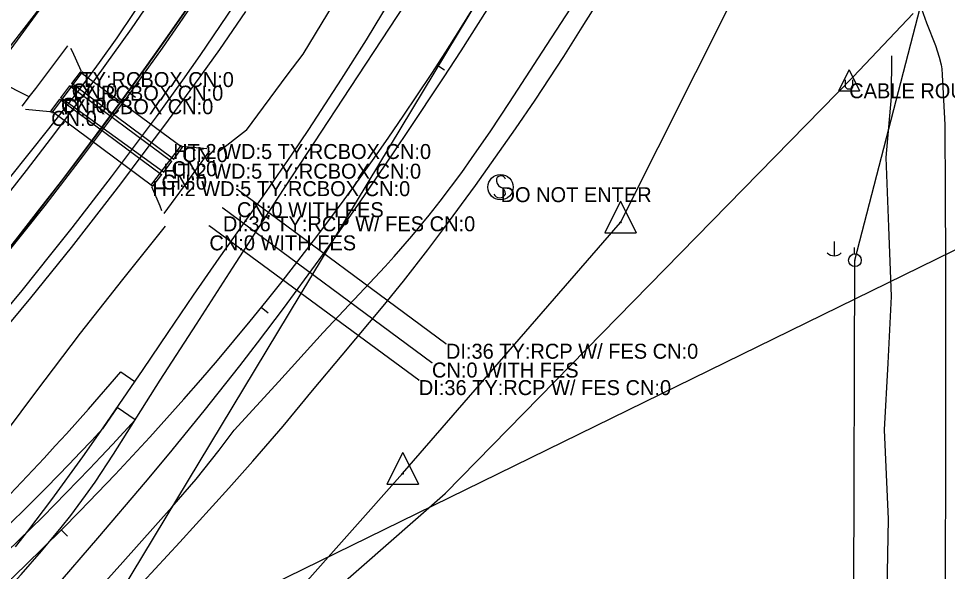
# Model space of a CAD drawing. Extents: x 1674300 to 1677920, y 225056 to 231852.
# Drawn here: x 1677063.6 to 1677374.1, y 227976.6 to 228161.2 of the extents above; entities that cross this region are included whole.
import ezdxf

# ---------------------------------------------------------------- set-up
doc = ezdxf.new("R2010")
doc.units = 0
for name, color, linetype in [('R_Horz Alg', 7, 'Continuous'), ('R_Horz Alg Annot', 7, 'Continuous'), ('R_Proposed Const Limits_Fill', 7, 'Continuous'), ('R_Proposed Road_Lane', 7, 'Continuous'), ('R_Proposed Road_Shoulder', 7, 'Continuous'), ('S_CROSS_DRAIN', 7, 'Continuous'), ('S_CROSS_DRAIN_ANNOT', 7, 'Continuous'), ('S_DITCHLINE', 7, 'Continuous'), ('S_DRG_PT_SYM', 7, 'Continuous'), ('S_EDGE_CONCRETE', 7, 'Continuous'), ('S_EDGE_PAVEMENT', 7, 'Continuous'), ('S_ELECTRIC_UTILITIES', 7, 'Continuous'), ('S_EXIST_ROW', 7, 'Continuous'), ('S_EXISTING_ALIGNMENT', 7, 'Continuous'), ('S_FIBER_OPTIC_CABLE', 7, 'Continuous'), ('S_HEADWALL', 7, 'Continuous'), ('S_PAVEMENT_CROWN', 7, 'Continuous'), ('S_SHOULDER', 7, 'Continuous'), ('S_SIGN', 7, 'Continuous'), ('S_SIGN_ANNOT', 7, 'Continuous'), ('S_UNDERGROUND_CABLE', 7, 'Continuous'), ('S_UTILITY_POLE', 7, 'Continuous'), ('S_UTILITY_POLE_ANNOT', 7, 'Continuous'), ('S_UTL_PT_SYM', 7, 'Continuous'), ('S_WALL', 7, 'Continuous')]:
    doc.layers.add(name, color=color, linetype=linetype)

msp = doc.modelspace()

# ---------------------------------------------------------------- linework, layer by layer
at = {"layer": 'R_Horz Alg'}
for centre, radius, end in [((1675928.16, 228988.54), 1449, 0.80558), ((1676402.48, 228665.51), 954.93, 328.88259)]:
    msp.add_arc(centre, radius, 296.0624, end, dxfattribs=at)
at = {"layer": 'R_Horz Alg Annot'}
for p, q in [((1677074.66, 227931.25), (1677220, 228172.01)), ((1676564.78, 227686.88), (1677389.93, 228090.45))]:
    msp.add_line(p, q, dxfattribs=at)
for points in [[(1677205.98, 228143.96), (1677203.46, 228145.59)], [(1677102.65, 228134.8), (1677100.23, 228136.57)], [(1677147.06, 228062.83), (1677144.73, 228064.72)], [(1677079.98, 227988.3), (1677077.86, 227990.42)]]:
    msp.add_lwpolyline(points, dxfattribs=at)
at = {"layer": 'R_Proposed Const Limits_Fill'}
msp.add_line((1677097.76, 228043.23), (1677102.49, 228039.99), dxfattribs=at)
msp.add_arc((1676364.65, 228668.23), 963.36, 309.06481, 319.55161, dxfattribs=at)
at = {"layer": 'R_Proposed Road_Lane'}
msp.add_lwpolyline([(1676953.5, 227863.64), (1676956.64, 227866.52), (1676972.6, 227881.4), (1676988.37, 227896.5), (1676996.17, 227904.12), (1677007.75, 227915.68), (1677022.13, 227930.45), (1677031.62, 227940.39), (1677041.04, 227950.41), (1677050.47, 227960.42), (1677064.47, 227975.57), (1677071.28, 227983.29), (1677077.87, 227991.2), (1677081.05, 227995.24), (1677086, 228001.89), (1677089.18, 228006.41), (1677095.28, 228015.66), (1677102.54, 228027.13)], dxfattribs=at)
msp.add_arc((1676402.48, 228665.51), 947.43, 296.0624, 317.63818, dxfattribs=at)
at = {"layer": 'R_Proposed Road_Shoulder'}
for p, q in [((1677096.51, 228031.26), (1677091.63, 228024.14)), ((1677102.54, 228027.13), (1677096.51, 228031.26))]:
    msp.add_line(p, q, dxfattribs=at)
msp.add_arc((1676402.48, 228665.51), 941.43, 296.0624, 317.05629, dxfattribs=at)
at = {"layer": 'S_CROSS_DRAIN'}
for p, q in [((1677081.37, 228139.53), (1677084.29, 228143.33)), ((1677084.29, 228143.33), (1677118.29, 228118.25)), ((1677077.78, 228134.74), (1677080.76, 228138.78)), ((1677080.76, 228138.78), (1677114.77, 228113.54)), ((1677115.37, 228114.19), (1677081.37, 228139.53)), ((1677074.5, 228130.35), (1677077.42, 228134.26)), ((1677077.42, 228134.26), (1677111.35, 228109.06)), ((1677112.01, 228109.92), (1677077.78, 228134.74)), ((1677108.35, 228105.25), (1677074.5, 228130.35)), ((1677118.29, 228118.25), (1677115.37, 228114.19)), ((1677114.77, 228113.54), (1677112.01, 228109.92)), ((1677111.35, 228109.06), (1677108.35, 228105.25)), ((1677206.45, 228052.59), (1677136.53, 228104.19)), ((1677131.86, 228097.96), (1677201.77, 228046.3)), ((1677197.38, 228040.44), (1677127.34, 228091.92))]:
    msp.add_line(p, q, dxfattribs=at)
at = {"layer": 'S_DITCHLINE'}
for points in [[(1677139.76, 228123.95), (1677153.43, 228142.29), (1677158.71, 228149.29), (1677171.09, 228169.75), (1677183.47, 228190.22), (1677194.37, 228204.93), (1677205.27, 228219.64), (1677214.14, 228234.4), (1677223.67, 228245.72)], [(1677066.9, 228135.11), (1677062.68, 228137.31), (1677055.92, 228140.95), (1677035.17, 228149.97), (1677018.6, 228154.56), (1676998.71, 228159.55)], [(1677353.55, 227946.6), (1677353.97, 227970.29), (1677354.38, 227993.98), (1677353.74, 228008.93), (1677353.09, 228023.88), (1677354.22, 228046.14), (1677355.36, 228068.4), (1677354.45, 228091.59), (1677353.55, 228114.78), (1677355.39, 228135.08), (1677355.46, 228148.71)], [(1677139.76, 228123.95), (1677130.25, 228116.51)], [(1677054.51, 228016.66), (1677069.4, 228036.4), (1677084.29, 228056.13), (1677098.48, 228074), (1677112.67, 228091.87)]]:
    msp.add_lwpolyline(points, dxfattribs=at)
at = {"layer": 'S_DRG_PT_SYM'}
for points in [[(1677084.29, 228143.33), (1677084.29, 228143.38), (1677084.29, 228143.33), (1677084.24, 228143.33), (1677084.29, 228143.33), (1677084.29, 228143.28), (1677084.29, 228143.33), (1677084.34, 228143.33)], [(1677080.76, 228138.78), (1677080.76, 228138.83), (1677080.76, 228138.78), (1677080.71, 228138.78), (1677080.76, 228138.78), (1677080.76, 228138.73), (1677080.76, 228138.78), (1677080.81, 228138.78)], [(1677081.37, 228139.53), (1677081.37, 228139.58), (1677081.37, 228139.53), (1677081.32, 228139.53), (1677081.37, 228139.53), (1677081.37, 228139.48), (1677081.37, 228139.53), (1677081.42, 228139.53)], [(1677077.42, 228134.26), (1677077.42, 228134.31), (1677077.42, 228134.26), (1677077.37, 228134.26), (1677077.42, 228134.26), (1677077.42, 228134.21), (1677077.42, 228134.26), (1677077.47, 228134.26)], [(1677077.78, 228134.74), (1677077.78, 228134.79), (1677077.78, 228134.74), (1677077.73, 228134.74), (1677077.78, 228134.74), (1677077.78, 228134.69), (1677077.78, 228134.74), (1677077.83, 228134.74)], [(1677074.5, 228130.35), (1677074.5, 228130.4), (1677074.5, 228130.35), (1677074.45, 228130.35), (1677074.5, 228130.35), (1677074.5, 228130.3), (1677074.5, 228130.35), (1677074.55, 228130.35)], [(1677118.29, 228118.25), (1677118.29, 228118.3), (1677118.29, 228118.25), (1677118.24, 228118.25), (1677118.29, 228118.25), (1677118.29, 228118.2), (1677118.29, 228118.25), (1677118.34, 228118.25)], [(1677114.77, 228113.54), (1677114.77, 228113.59), (1677114.77, 228113.54), (1677114.72, 228113.54), (1677114.77, 228113.54), (1677114.77, 228113.49), (1677114.77, 228113.54), (1677114.82, 228113.54)], [(1677115.37, 228114.19), (1677115.37, 228114.24), (1677115.37, 228114.19), (1677115.32, 228114.19), (1677115.37, 228114.19), (1677115.37, 228114.14), (1677115.37, 228114.19), (1677115.42, 228114.19)], [(1677111.35, 228109.06), (1677111.35, 228109.11), (1677111.35, 228109.06), (1677111.3, 228109.06), (1677111.35, 228109.06), (1677111.35, 228109.01), (1677111.35, 228109.06), (1677111.4, 228109.06)], [(1677112.01, 228109.92), (1677112.01, 228109.97), (1677112.01, 228109.92), (1677111.96, 228109.92), (1677112.01, 228109.92), (1677112.01, 228109.87), (1677112.01, 228109.92), (1677112.06, 228109.92)], [(1677108.35, 228105.25), (1677108.35, 228105.3), (1677108.35, 228105.25), (1677108.3, 228105.25), (1677108.35, 228105.25), (1677108.35, 228105.2), (1677108.35, 228105.25), (1677108.4, 228105.25)], [(1677136.53, 228104.19), (1677136.53, 228104.24), (1677136.53, 228104.19), (1677136.48, 228104.19), (1677136.53, 228104.19), (1677136.53, 228104.14), (1677136.53, 228104.19), (1677136.58, 228104.19)], [(1677131.86, 228097.96), (1677131.86, 228098.01), (1677131.86, 228097.96), (1677131.81, 228097.96), (1677131.86, 228097.96), (1677131.86, 228097.91), (1677131.86, 228097.96), (1677131.91, 228097.96)], [(1677127.34, 228091.92), (1677127.34, 228091.97), (1677127.34, 228091.92), (1677127.29, 228091.92), (1677127.34, 228091.92), (1677127.34, 228091.87), (1677127.34, 228091.92), (1677127.39, 228091.92)], [(1677206.45, 228052.59), (1677206.45, 228052.64), (1677206.45, 228052.59), (1677206.4, 228052.59), (1677206.45, 228052.59), (1677206.45, 228052.54), (1677206.45, 228052.59), (1677206.5, 228052.59)], [(1677201.77, 228046.3), (1677201.77, 228046.35), (1677201.77, 228046.3), (1677201.72, 228046.3), (1677201.77, 228046.3), (1677201.77, 228046.25), (1677201.77, 228046.3), (1677201.82, 228046.3)], [(1677197.38, 228040.44), (1677197.38, 228040.49), (1677197.38, 228040.44), (1677197.33, 228040.44), (1677197.38, 228040.44), (1677197.38, 228040.39), (1677197.38, 228040.44), (1677197.43, 228040.44)]]:
    msp.add_lwpolyline(points, dxfattribs=at)
at = {"layer": 'S_EDGE_CONCRETE'}
for points in [[(1677064.84, 228131.91), (1677067.61, 228135.63), (1677069.42, 228137.82), (1677080.04, 228152.09)], [(1677112.31, 228096.12), (1677119.95, 228106.6), (1677127.58, 228117.07)]]:
    msp.add_lwpolyline(points, dxfattribs=at)
at = {"layer": 'S_EDGE_PAVEMENT'}
for points in [[(1677059.75, 228102.25), (1677066.21, 228110.42), (1677075.74, 228122.78), (1677080.32, 228128.89), (1677089.37, 228141.18), (1677101.3, 228157.81), (1677107.16, 228166.19), (1677115.82, 228178.85), (1677124.4, 228191.78), (1677130.03, 228200.46), (1677141.07, 228217.94), (1677147.6, 228228.52), (1677160.44, 228249.79), (1677172.59, 228270.43), (1677178.55, 228280.82), (1677186.05, 228294.21), (1677190.97, 228303.18)], [(1677054.49, 228057.98), (1677064.77, 228070.36), (1677074.88, 228082.91), (1677081.54, 228091.34), (1677094.67, 228108.34), (1677104.72, 228121.64), (1677109.67, 228128.34), (1677118.48, 228140.59), (1677124.25, 228148.83), (1677135.54, 228165.49), (1677144.07, 228178.51), (1677152.42, 228191.65), (1677160.77, 228204.79), (1677173.76, 228225.6), (1677180.15, 228236.06), (1677186.55, 228246.75), (1677199.05, 228268.29)], [(1677050.47, 227960.42), (1677064.47, 227975.57), (1677071.28, 227983.29), (1677077.87, 227991.2), (1677081.05, 227995.24), (1677086, 228001.89), (1677089.18, 228006.41), (1677095.28, 228015.66), (1677103.13, 228028.07), (1677110.98, 228040.48), (1677123.03, 228059.15), (1677135.07, 228077.82), (1677142.69, 228089.53), (1677150.3, 228101.23), (1677162.42, 228119.68), (1677174.53, 228138.13), (1677187.58, 228158.03), (1677200.63, 228177.93), (1677210.53, 228193.87), (1677220.43, 228209.81), (1677230.72, 228227.78), (1677241.01, 228245.75)], [(1677363.19, 228170.78), (1677367.12, 228159.82), (1677370.1, 228152.18), (1677371.35, 228148.32), (1677371.96, 228145.71), (1677372.17, 228144.39), (1677372.37, 228142.38), (1677373.23, 228125.66), (1677373.35, 228102.82), (1677373.48, 228079.98), (1677373.48, 228067.05), (1677373.48, 228054.12), (1677373.48, 228041.18), (1677373.48, 228028.25), (1677373.43, 228014.55), (1677373.39, 228000.85), (1677373.34, 227987.15), (1677373.29, 227973.45)], [(1677090.78, 227971.04), (1677098.41, 227979.59), (1677114.88, 227998.02), (1677122.91, 228007.41), (1677128.1, 228013.8), (1677130.63, 228017.04), (1677134.35, 228021.97), (1677135.63, 228023.72), (1677150.54, 228040.03), (1677165.44, 228056.33), (1677175.81, 228067.37), (1677186.18, 228078.41), (1677189.19, 228081.76), (1677195.08, 228088.56), (1677200.8, 228095.52), (1677204.51, 228100.23), (1677211.72, 228109.83), (1677215.01, 228114.43), (1677221.43, 228123.74), (1677227.68, 228133.17), (1677240.04, 228152.19), (1677249.84, 228167.22)]]:
    msp.add_lwpolyline(points, dxfattribs=at)
at = {"layer": 'S_ELECTRIC_UTILITIES'}
for p, q in [((1677343.16, 228080.48), (1677425.49, 228399.8)), ((1677342.78, 227946.34), (1677343.16, 228080.48))]:
    msp.add_line(p, q, dxfattribs=at)
at = {"layer": 'S_EXIST_ROW'}
for p, q in [((1677264.8, 228093.13), (1677314.69, 228192.42)), ((1677264.82, 228100.22), (1677259.53, 228089.59)), ((1677264.82, 228100.22), (1677270.05, 228089.59)), ((1677191.98, 228009.21), (1677264.8, 228093.13)), ((1677264.8, 228093.13), (1677264.8, 228093.13)), ((1677259.53, 228089.59), (1677270.05, 228089.59)), ((1677192, 228016.3), (1677186.71, 228005.66)), ((1677192, 228016.3), (1677197.23, 228005.66)), ((1677045.25, 227844.61), (1677191.98, 228009.21)), ((1677191.98, 228009.21), (1677191.98, 228009.21)), ((1677186.71, 228005.66), (1677197.23, 228005.66))]:
    msp.add_line(p, q, dxfattribs=at)
for centre, radius in [((1677264.8, 228093.13), 0.18), ((1677264.8, 228093.13), 0.09), ((1677191.98, 228009.21), 0.18), ((1677191.98, 228009.21), 0.09)]:
    msp.add_circle(centre, radius, dxfattribs=at)
msp.add_arc((1675926.71, 228989.39), 1410.53, 295.94359, 0.85682, dxfattribs=at)
at = {"layer": 'S_EXISTING_ALIGNMENT'}
msp.add_arc((1675926.71, 228989.39), 1450.53, 315.98862, 345.81316, dxfattribs=at)
at = {"layer": 'S_FIBER_OPTIC_CABLE'}
for p, q in [((1677055.89, 228145.71), (1677094.67, 228195.4)), ((1677342.55, 228141.77), (1677362.65, 228162.87)), ((1677206.22, 228002.56), (1677342.55, 228141.77)), ((1677124.03, 227930.86), (1677206.22, 228002.56))]:
    msp.add_line(p, q, dxfattribs=at)
at = {"layer": 'S_HEADWALL'}
for points in [[(1677074.7, 228129.63), (1677085.08, 228143.46)], [(1677107.83, 228105.42), (1677118.07, 228118.88)]]:
    msp.add_lwpolyline(points, dxfattribs=at)
at = {"layer": 'S_PAVEMENT_CROWN'}
for points in [[(1677055.98, 228078.31), (1677065.91, 228090.56), (1677072.44, 228098.8), (1677085.3, 228115.44), (1677099.96, 228135.04), (1677111.69, 228151.31), (1677117.43, 228159.53), (1677125.9, 228171.96), (1677134.43, 228184.91), (1677142.78, 228197.98), (1677151.13, 228211.05), (1677157.77, 228221.65), (1677164.42, 228232.25), (1677170.89, 228242.95), (1677176.98, 228253.45), (1677188.82, 228274.65), (1677196.51, 228288.75), (1677204.2, 228302.85)], [(1677075.53, 227970.74), (1677090.09, 227987.61), (1677106.02, 228006.41), (1677113.9, 228015.87), (1677125.58, 228030.19), (1677137.53, 228045.26), (1677143.42, 228052.86), (1677152.14, 228064.35), (1677164.1, 228080.61), (1677169.97, 228088.81), (1677178, 228100.29), (1677185.87, 228111.87), (1677193.73, 228123.46), (1677205.64, 228141.43), (1677211.52, 228150.46), (1677220.23, 228164.08)]]:
    msp.add_lwpolyline(points, dxfattribs=at)
at = {"layer": 'S_SHOULDER'}
for points in [[(1677060.59, 228107.91), (1677073.75, 228124.38), (1677083.08, 228136.31), (1677087.63, 228142.35), (1677090.64, 228146.47), (1677096.51, 228154.8), (1677102.23, 228163.25), (1677113.4, 228180.31), (1677121.81, 228193.39), (1677130.22, 228206.46), (1677138.54, 228219.58), (1677151.45, 228240.47), (1677157.74, 228251), (1677163.82, 228261.48), (1677175.7, 228282.6), (1677183.02, 228295.95), (1677190.34, 228309.3)], [(1677062.58, 227984.81), (1677066.67, 227990.02), (1677074.69, 228000.56), (1677085.1, 228014.86), (1677091.88, 228024.5), (1677105.21, 228043.97), (1677113.63, 228056.4), (1677122.05, 228068.83), (1677130.61, 228081.17), (1677138.55, 228092.33), (1677146.5, 228103.49), (1677155.05, 228115.85), (1677160.65, 228124.16), (1677171.59, 228140.95), (1677179.87, 228154.1), (1677187.96, 228167.37), (1677196.06, 228180.63), (1677205.85, 228196.84), (1677215.64, 228213.05), (1677226.95, 228234.53), (1677238.26, 228256)], [(1677105.11, 227972.94), (1677117.45, 227986.37), (1677133.87, 228004.3), (1677141.95, 228013.38), (1677151.99, 228025.08), (1677161.88, 228036.93), (1677171.77, 228048.77), (1677185.48, 228065.18), (1677192.22, 228073.46), (1677200.44, 228083.99), (1677205.8, 228091.1), (1677216.32, 228105.47), (1677229.71, 228124.4), (1677236.26, 228133.97), (1677245.82, 228148.48), (1677252.02, 228158.3), (1677260.19, 228171.46)], [(1677057.33, 228055.54), (1677067.66, 228067.94), (1677081.24, 228084.7), (1677087.91, 228093.17), (1677097.78, 228105.99), (1677105.28, 228116.03), (1677112.78, 228126.08), (1677124.9, 228142.55), (1677130.84, 228150.88), (1677136.66, 228159.31), (1677139.51, 228163.58)]]:
    msp.add_lwpolyline(points, dxfattribs=at)
at = {"layer": 'S_SIGN'}
msp.add_circle((1677224.7, 228104.88), 4.24, dxfattribs=at)
for centre, radius, start, end in [((1677225.87, 228107.14), 2.55, 167.1196, 241.9813), ((1677224.83, 228107.04), 1.62, 16.5258, 156.8957), ((1677224, 228102.6), 2.38, 358.6529, 73.7063), ((1677224.44, 228103.48), 2.17, 204.641, 335.359)]:
    msp.add_arc(centre, radius, start, end, dxfattribs=at)
at = {"layer": 'S_UNDERGROUND_CABLE'}
for p, q in [((1677341.24, 228144.11), (1677337.71, 228137.02)), ((1677341.24, 228144.11), (1677344.73, 228137.02)), ((1677340.04, 228138.26), (1677340.04, 228140.7)), ((1677340.66, 228137.6), (1677340.04, 228138.26)), ((1677342.4, 228138.26), (1677341.86, 228137.6)), ((1677342.4, 228140.7), (1677342.4, 228138.26)), ((1677337.71, 228137.02), (1677344.73, 228137.02)), ((1677341.86, 228137.6), (1677340.66, 228137.6))]:
    msp.add_line(p, q, dxfattribs=at)
at = {"layer": 'S_UTILITY_POLE'}
for p, q in [((1677336.19, 228086.7), (1677336.19, 228081.97)), ((1677343.03, 228082.63), (1677343.03, 228084.74))]:
    msp.add_line(p, q, dxfattribs=at)
msp.add_circle((1677343.16, 228080.49), 2.13, dxfattribs=at)
msp.add_arc((1677336.25, 228085.4), 3.41, 226.3972, 313.6028, dxfattribs=at)
at = {"layer": 'S_UTL_PT_SYM'}
for points in [[(1677342.55, 228141.77), (1677342.55, 228141.82), (1677342.55, 228141.77), (1677342.5, 228141.77), (1677342.55, 228141.77), (1677342.55, 228141.72), (1677342.55, 228141.77), (1677342.6, 228141.77)], [(1677343.16, 228080.48), (1677343.16, 228080.53), (1677343.16, 228080.48), (1677343.11, 228080.48), (1677343.16, 228080.48), (1677343.16, 228080.43), (1677343.16, 228080.48), (1677343.21, 228080.48)], [(1677206.22, 228002.56), (1677206.22, 228002.61), (1677206.22, 228002.56), (1677206.17, 228002.56), (1677206.22, 228002.56), (1677206.22, 228002.51), (1677206.22, 228002.56), (1677206.27, 228002.56)]]:
    msp.add_lwpolyline(points, dxfattribs=at)
at = {"layer": 'S_WALL'}
for points in [[(1677084.57, 228143.62), (1677084.49, 228143.73), (1677081.62, 228150.16), (1677081.11, 228151.19)], [(1677065.93, 228130.98), (1677074.09, 228130.17), (1677074.39, 228130.01)], [(1677118.3, 228118.57), (1677126.55, 228117.8)], [(1677111.53, 228097.03), (1677110.91, 228098.49), (1677108.1, 228105.02)]]:
    msp.add_lwpolyline(points, dxfattribs=at)

# ---------------------------------------------------------------- texts
at = {"layer": 'S_CROSS_DRAIN_ANNOT'}
for s, p in [('TY:RCBOX CN:0', (1677084.29, 228138.33)), ('TY:RCBOX CN:0', (1677080.76, 228133.78)), ('CN:0', (1677081.37, 228134.53)), ('TY:RCBOX CN:0', (1677077.42, 228129.26)), ('CN:0', (1677077.78, 228129.74)), ('CN:0', (1677074.5, 228125.35)), ('HT:2 WD:5 TY:RCBOX CN:0', (1677115.29, 228114.29)), ('CN:0', (1677118.29, 228113.25)), ('CN:0', (1677114.77, 228108.54)), ('HT:2 WD:5 TY:RCBOX CN:0', (1677111.96, 228107.72)), ('CN:0', (1677111.35, 228104.06)), ('HT:2 WD:5 TY:RCBOX CN:0', (1677108.32, 228101.89)), ('CN:0 WITH FES', (1677136.61, 228094.86)), ('DI:36 TY:RCP W/ FES CN:0', (1677131.9, 228090.15)), ('CN:0 WITH FES', (1677127.39, 228083.78)), ('DI:36 TY:RCP W/ FES CN:0', (1677206.45, 228047.59)), ('CN:0 WITH FES', (1677201.77, 228041.3)), ('DI:36 TY:RCP W/ FES CN:0', (1677197.38, 228035.44))]:
    msp.add_text(s, height=5, rotation=360, dxfattribs=at).set_placement(p)
at = {"layer": 'S_SIGN_ANNOT'}
msp.add_text('DO NOT ENTER', height=5, rotation=360, dxfattribs=at).set_placement((1677224.7, 228099.88))
at = {"layer": 'S_UTILITY_POLE_ANNOT'}
msp.add_text('CABLE ROUTE NE/SW', height=5, rotation=360, dxfattribs=at).set_placement((1677341.24, 228134.58))

doc.saveas('drawing.dxf')
